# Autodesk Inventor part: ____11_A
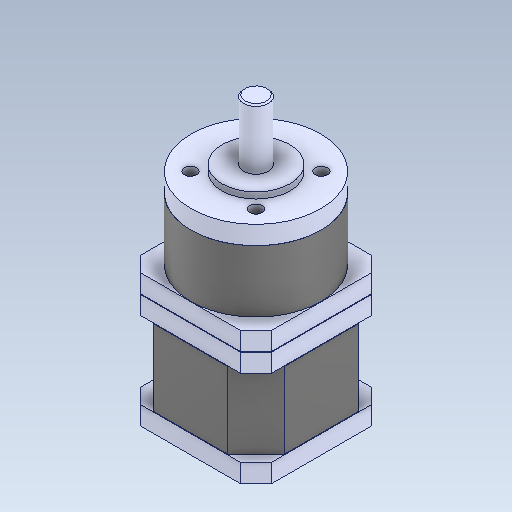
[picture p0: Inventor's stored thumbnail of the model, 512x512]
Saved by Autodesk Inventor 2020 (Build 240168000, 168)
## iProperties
Created: 2017-09
Part Number: ____11_A
Material: Générique
Document SubType Name: Modeling
Designer: bruno
Density: 1 g/cm^3
Appearance: Par défaut
Author: bruno
Sending System: SolidWorks 2016
Last Author: Prof
Last Saved: 2018-10-03
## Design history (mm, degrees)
feature "Importée1"
node "Solide1"
